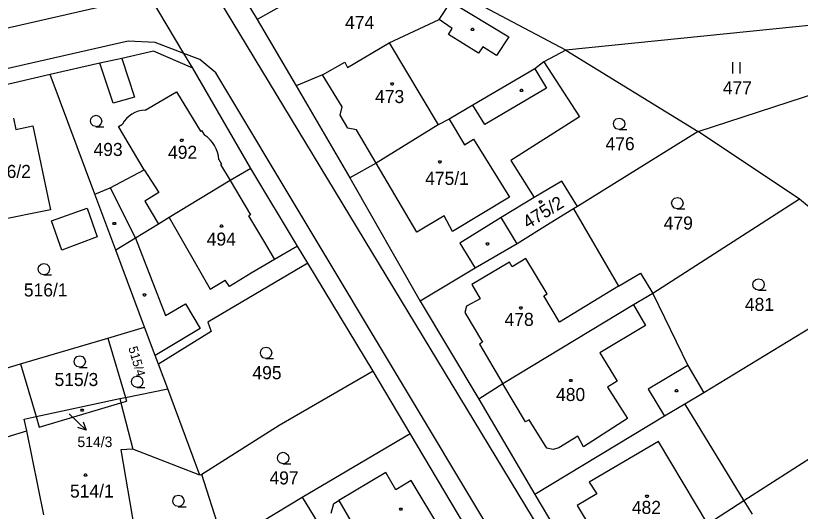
# Model space of a CAD drawing. Extents: x -621797 to -620972, y -1175539 to -1174697.
# Drawn here: x -621483.9 to -621381.7, y -1174869.1 to -1174804.6 of the extents above; entities that cross this region are included whole.
import ezdxf

# ---------------------------------------------------------------- set-up
doc = ezdxf.new("R2010")
doc.units = 0
for name, color, linetype in [('INZ mimo EON - nadz', 7, 'Continuous'), ('Rozvod plynu EON', 7, 'Continuous'), ('SDEL EON', 7, 'Continuous'), ('SDEL EON - popis', 7, 'Continuous'), ('Silnoproud EON', 7, 'Continuous'), ('Silnoproud EON - popis', 7, 'Continuous')]:
    doc.layers.add(name, color=color, linetype=linetype)

msp = doc.modelspace()

# ---------------------------------------------------------------- linework, layer by layer
at = {"layer": 'INZ mimo EON - nadz'}
for p in [(-621476.92, -1174856.48), (-621474.718, -1174858.549)]:
    msp.add_line(p, (-621476.9, -1174856.49), dxfattribs=at)
msp.add_lwpolyline([(-621475.102, -1174857.499), (-621474.718, -1174858.549), (-621475.789, -1174858.226)], dxfattribs=at)
at = {"layer": 'Rozvod plynu EON'}
for points in [[(-621424.32, -1174806.24), (-621424.23, -1174806.39), (-621424.32, -1174806.54), (-621424.5, -1174806.54), (-621424.59, -1174806.39), (-621424.5, -1174806.24)], [(-621434.78, -1174813.34), (-621434.69, -1174813.49), (-621434.78, -1174813.64), (-621434.96, -1174813.64), (-621435.05, -1174813.49), (-621434.96, -1174813.34)], [(-621417.95, -1174814.18), (-621417.86, -1174814.33), (-621417.95, -1174814.48), (-621418.13, -1174814.48), (-621418.22, -1174814.33), (-621418.13, -1174814.18)], [(-621462.18, -1174820.67), (-621462.09, -1174820.82), (-621462.18, -1174820.97), (-621462.36, -1174820.97), (-621462.45, -1174820.82), (-621462.36, -1174820.67)], [(-621428.58, -1174823.49), (-621428.49, -1174823.64), (-621428.58, -1174823.79), (-621428.76, -1174823.79), (-621428.85, -1174823.64), (-621428.76, -1174823.49)], [(-621415.48, -1174828.7), (-621415.39, -1174828.85), (-621415.48, -1174829), (-621415.66, -1174829), (-621415.75, -1174828.85), (-621415.66, -1174828.7)], [(-621470.95, -1174831.51), (-621470.86, -1174831.66), (-621470.95, -1174831.81), (-621471.13, -1174831.81), (-621471.22, -1174831.66), (-621471.13, -1174831.51)], [(-621457.01, -1174831.85), (-621456.92, -1174832), (-621457.01, -1174832.15), (-621457.19, -1174832.15), (-621457.28, -1174832), (-621457.19, -1174831.85)], [(-621422.36, -1174834.16), (-621422.27, -1174834.31), (-621422.36, -1174834.46), (-621422.54, -1174834.46), (-621422.63, -1174834.31), (-621422.54, -1174834.16)], [(-621467.03, -1174840.81), (-621466.94, -1174840.96), (-621467.03, -1174841.11), (-621467.21, -1174841.11), (-621467.3, -1174840.96), (-621467.21, -1174840.81)], [(-621418.02, -1174842.51), (-621417.93, -1174842.66), (-621418.02, -1174842.81), (-621418.2, -1174842.81), (-621418.29, -1174842.66), (-621418.2, -1174842.51)], [(-621411.53, -1174851.95), (-621411.44, -1174852.1), (-621411.53, -1174852.25), (-621411.71, -1174852.25), (-621411.8, -1174852.1), (-621411.71, -1174851.95)], [(-621397.77, -1174853.29), (-621397.68, -1174853.44), (-621397.77, -1174853.59), (-621397.95, -1174853.59), (-621398.04, -1174853.44), (-621397.95, -1174853.29)], [(-621475.13, -1174855.81), (-621475.04, -1174855.96), (-621475.13, -1174856.11), (-621475.31, -1174856.11), (-621475.4, -1174855.96), (-621475.31, -1174855.81)], [(-621474.72, -1174864.27), (-621474.63, -1174864.42), (-621474.72, -1174864.57), (-621474.9, -1174864.57), (-621474.99, -1174864.42), (-621474.9, -1174864.27)], [(-621401.6, -1174867.01), (-621401.51, -1174867.16), (-621401.6, -1174867.31), (-621401.78, -1174867.31), (-621401.87, -1174867.16), (-621401.78, -1174867.01)], [(-621433.66, -1174868.7), (-621433.57, -1174868.85), (-621433.66, -1174869), (-621433.84, -1174869), (-621433.93, -1174868.85), (-621433.84, -1174868.7)]]:
    msp.add_lwpolyline(points, close=True, dxfattribs=at)
at = {"layer": 'SDEL EON'}
for p, q in [((-621390.54, -1174810.65), (-621390.54, -1174812.15)), ((-621389.54, -1174812.15), (-621389.54, -1174810.65))]:
    msp.add_line(p, q, dxfattribs=at)
for points in [[(-621473.41, -1174819.05), (-621473.79, -1174818.95), (-621474.06, -1174818.68), (-621474.16, -1174818.31), (-621474.06, -1174817.94), (-621473.79, -1174817.67), (-621473.42, -1174817.57), (-621473.05, -1174817.67), (-621472.78, -1174817.94), (-621472.68, -1174818.32), (-621472.78, -1174818.7), (-621473.05, -1174818.97), (-621473.43, -1174819.07), (-621472.43, -1174819.07)], [(-621405.31, -1174819.42), (-621405.69, -1174819.32), (-621405.96, -1174819.05), (-621406.06, -1174818.68), (-621405.96, -1174818.31), (-621405.69, -1174818.04), (-621405.32, -1174817.94), (-621404.95, -1174818.04), (-621404.68, -1174818.31), (-621404.58, -1174818.69), (-621404.68, -1174819.07), (-621404.95, -1174819.34), (-621405.33, -1174819.44), (-621404.33, -1174819.44)], [(-621397.73, -1174829.75), (-621398.11, -1174829.65), (-621398.38, -1174829.38), (-621398.48, -1174829.01), (-621398.38, -1174828.64), (-621398.11, -1174828.37), (-621397.74, -1174828.27), (-621397.37, -1174828.37), (-621397.1, -1174828.64), (-621397, -1174829.02), (-621397.1, -1174829.4), (-621397.37, -1174829.67), (-621397.75, -1174829.77), (-621396.75, -1174829.77)], [(-621480.21, -1174838.34), (-621480.59, -1174838.24), (-621480.86, -1174837.97), (-621480.96, -1174837.6), (-621480.86, -1174837.23), (-621480.59, -1174836.96), (-621480.22, -1174836.86), (-621479.85, -1174836.96), (-621479.58, -1174837.23), (-621479.48, -1174837.61), (-621479.58, -1174837.99), (-621479.85, -1174838.26), (-621480.23, -1174838.36), (-621479.23, -1174838.36)], [(-621387.16, -1174840.34), (-621387.54, -1174840.24), (-621387.81, -1174839.97), (-621387.91, -1174839.6), (-621387.81, -1174839.23), (-621387.54, -1174838.96), (-621387.17, -1174838.86), (-621386.8, -1174838.96), (-621386.53, -1174839.23), (-621386.43, -1174839.61), (-621386.53, -1174839.99), (-621386.8, -1174840.26), (-621387.18, -1174840.36), (-621386.18, -1174840.36)], [(-621451.28, -1174849.23), (-621451.66, -1174849.13), (-621451.93, -1174848.86), (-621452.03, -1174848.49), (-621451.93, -1174848.12), (-621451.66, -1174847.85), (-621451.29, -1174847.75), (-621450.92, -1174847.85), (-621450.65, -1174848.12), (-621450.55, -1174848.5), (-621450.65, -1174848.88), (-621450.92, -1174849.15), (-621451.3, -1174849.25), (-621450.3, -1174849.25)], [(-621475.54, -1174850.37), (-621475.92, -1174850.27), (-621476.19, -1174850), (-621476.29, -1174849.63), (-621476.19, -1174849.26), (-621475.92, -1174848.99), (-621475.55, -1174848.89), (-621475.18, -1174848.99), (-621474.91, -1174849.26), (-621474.81, -1174849.64), (-621474.91, -1174850.02), (-621475.18, -1174850.29), (-621475.56, -1174850.39), (-621474.56, -1174850.39)], [(-621468.06, -1174853), (-621468.44, -1174852.9), (-621468.71, -1174852.63), (-621468.81, -1174852.26), (-621468.71, -1174851.89), (-621468.44, -1174851.62), (-621468.07, -1174851.52), (-621467.7, -1174851.62), (-621467.43, -1174851.89), (-621467.33, -1174852.27), (-621467.43, -1174852.65), (-621467.7, -1174852.92), (-621468.08, -1174853.02), (-621467.08, -1174853.02)], [(-621449.06, -1174862.93), (-621449.44, -1174862.83), (-621449.71, -1174862.56), (-621449.81, -1174862.19), (-621449.71, -1174861.82), (-621449.44, -1174861.55), (-621449.07, -1174861.45), (-621448.7, -1174861.55), (-621448.43, -1174861.82), (-621448.33, -1174862.2), (-621448.43, -1174862.58), (-621448.7, -1174862.85), (-621449.08, -1174862.95), (-621448.08, -1174862.95)], [(-621462.69, -1174868.51), (-621463.07, -1174868.41), (-621463.34, -1174868.14), (-621463.44, -1174867.77), (-621463.34, -1174867.4), (-621463.07, -1174867.13), (-621462.7, -1174867.03), (-621462.33, -1174867.13), (-621462.06, -1174867.4), (-621461.96, -1174867.78), (-621462.06, -1174868.16), (-621462.33, -1174868.43), (-621462.71, -1174868.53), (-621461.71, -1174868.53)]]:
    msp.add_lwpolyline(points, dxfattribs=at)
at = {"layer": 'SDEL EON - popis'}
for p, q in [((-621461.85, -1174795.25), (-621402.58, -1174893.11)), ((-621470.29, -1174802.9), (-621493.86, -1174808.23)), ((-621427.21, -1174802.78), (-621419.69, -1174807.36)), ((-621427.04, -1174806.26), (-621428.73, -1174805.08)), ((-621427.53, -1174807.05), (-621427.04, -1174806.26)), ((-621423.62, -1174809.49), (-621427.53, -1174807.05)), ((-621469.26, -1174807.94), (-621494.45, -1174813.64)), ((-621465.74, -1174808.08), (-621469.26, -1174807.94)), ((-621461.99, -1174809.51), (-621465.74, -1174808.08)), ((-621435.27, -1174808.14), (-621428.88, -1174818.81)), ((-621419.69, -1174807.36), (-621421.27, -1174809.78)), ((-621423.08, -1174808.64), (-621423.62, -1174809.49)), ((-621421.27, -1174809.78), (-621423.08, -1174808.64)), ((-621470.08, -1174810.16), (-621468.43, -1174815.23)), ((-621459.93, -1174810.3), (-621461.99, -1174809.51)), ((-621457.84, -1174812.05), (-621459.93, -1174810.3)), ((-621471.21, -1174815.98), (-621472.93, -1174810.8)), ((-621392.36, -1174921.13), (-621457.84, -1174812.05)), ((-621443.95, -1174812.29), (-621447.38, -1174813.75)), ((-621416.28, -1174811.51), (-621414.78, -1174814.06)), ((-621414.78, -1174814.06), (-621422.81, -1174818.77)), ((-621468.43, -1174815.23), (-621471.21, -1174815.98)), ((-621422.81, -1174818.77), (-621424.37, -1174816.27)), ((-621427.44, -1174818.06), (-621425.44, -1174821.41)), ((-621425.44, -1174821.41), (-621424.28, -1174820.7)), ((-621424.28, -1174820.7), (-621419.61, -1174828.25)), ((-621467.15, -1174824.67), (-621465.25, -1174827.64)), ((-621431.67, -1174832.78), (-621436.97, -1174823.79)), ((-621455.96, -1174826.08), (-621453.31, -1174830.52)), ((-621471.6, -1174827.03), (-621468.28, -1174833.55)), ((-621465.25, -1174827.64), (-621467.05, -1174828.75)), ((-621467.05, -1174828.75), (-621465.29, -1174831.73)), ((-621419.61, -1174828.25), (-621427.01, -1174832.68)), ((-621479.22, -1174831.31), (-621474.57, -1174829.67)), ((-621474.57, -1174829.67), (-621473.28, -1174833.39)), ((-621453.31, -1174830.52), (-621453.56, -1174830.68)), ((-621453.56, -1174830.68), (-621451.63, -1174833.91)), ((-621428.09, -1174830.67), (-621431.67, -1174832.78)), ((-621427.01, -1174832.68), (-621428.09, -1174830.67)), ((-621477.87, -1174835.14), (-621479.22, -1174831.31)), ((-621463.91, -1174830.89), (-621458.58, -1174840.2)), ((-621418.58, -1174834.29), (-621420.66, -1174830.86)), ((-621473.28, -1174833.39), (-621477.87, -1174835.14)), ((-621468.28, -1174833.55), (-621464.38, -1174843.62)), ((-621451.63, -1174833.91), (-621450.18, -1174836.35)), ((-621447.19, -1174834.59), (-621450.18, -1174836.35)), ((-621450.18, -1174836.35), (-621453.21, -1174838.14)), ((-621419.59, -1174836.71), (-621424.49, -1174839.62)), ((-621419.24, -1174837.29), (-621419.59, -1174836.71)), ((-621417.46, -1174836.23), (-621419.24, -1174837.29)), ((-621414.69, -1174840.81), (-621417.46, -1174836.23)), ((-621453.21, -1174838.14), (-621456.04, -1174839.88)), ((-621458.58, -1174840.2), (-621456.62, -1174839.03)), ((-621456.04, -1174839.88), (-621456.62, -1174839.03)), ((-621424.49, -1174839.62), (-621423.43, -1174841.45)), ((-621405.38, -1174839.83), (-621413.08, -1174844.49)), ((-621415.12, -1174841.06), (-621414.69, -1174840.81)), ((-621413.08, -1174844.49), (-621415.12, -1174841.06)), ((-621423.43, -1174841.45), (-621425.17, -1174842.43)), ((-621464.38, -1174843.62), (-621461.77, -1174842.1)), ((-621461.77, -1174842.1), (-621459.85, -1174845.33)), ((-621425.17, -1174842.43), (-621425.4, -1174843.24)), ((-621403.43, -1174842.24), (-621401.87, -1174844.94)), ((-621425.4, -1174843.24), (-621423.12, -1174847.09)), ((-621401.87, -1174844.94), (-621407.81, -1174848.5)), ((-621459.85, -1174845.33), (-621465.73, -1174848.83)), ((-621423.12, -1174847.09), (-621423.52, -1174847.39)), ((-621423.52, -1174847.39), (-621420.46, -1174852.54)), ((-621407.81, -1174848.5), (-621405.59, -1174852.18)), ((-621396.36, -1174850.15), (-621401.55, -1174853.22)), ((-621405.59, -1174852.18), (-621406.82, -1174852.97)), ((-621417.49, -1174857.5), (-621420.46, -1174852.54)), ((-621406.82, -1174852.97), (-621404.22, -1174857.05)), ((-621401.55, -1174853.22), (-621399.43, -1174856.74)), ((-621470.33, -1174854.45), (-621470.18, -1174855.02)), ((-621470.18, -1174855.02), (-621468.62, -1174861.06)), ((-621417.03, -1174857.22), (-621417.49, -1174857.5)), ((-621414.72, -1174860.93), (-621417.03, -1174857.22)), ((-621404.22, -1174857.05), (-621409.94, -1174860.73)), ((-621410.68, -1174859.34), (-621413.15, -1174860.88)), ((-621409.94, -1174860.73), (-621410.68, -1174859.34)), ((-621400.21, -1174860.03), (-621409.2, -1174865.35)), ((-621393.76, -1174870.81), (-621400.21, -1174860.03)), ((-621413.92, -1174861.09), (-621414.72, -1174860.93)), ((-621413.15, -1174860.88), (-621413.92, -1174861.09)), ((-621435.71, -1174864.09), (-621441.83, -1174867.74)), ((-621434.4, -1174866.33), (-621435.71, -1174864.09)), ((-621432.38, -1174865.12), (-621434.4, -1174866.33)), ((-621427.89, -1174872.59), (-621432.38, -1174865.12)), ((-621409.2, -1174865.35), (-621408.22, -1174866.85)), ((-621408.22, -1174866.85), (-621410.77, -1174868.36)), ((-621410.77, -1174868.36), (-621407.68, -1174873.5))]:
    msp.add_line(p, q, dxfattribs=at)
at = {"layer": 'Silnoproud EON'}
for p, q in [((-621458.69, -1174794.8), (-621452.45, -1174805.11)), ((-621461.99, -1174809.51), (-621468.3, -1174798.95)), ((-621445.02, -1174800.92), (-621452.45, -1174805.11)), ((-621412.27, -1174809.1), (-621426.41, -1174801.58)), ((-621428.73, -1174805.08), (-621427.21, -1174802.78)), ((-621452.45, -1174805.11), (-621447.38, -1174813.75)), ((-621435.27, -1174808.14), (-621428.73, -1174805.08)), ((-621378.63, -1174805.68), (-621412.27, -1174809.1)), ((-621440.69, -1174811.33), (-621435.27, -1174808.14)), ((-621465.93, -1174809.22), (-621470.08, -1174810.16)), ((-621460.83, -1174811.45), (-621465.93, -1174809.22)), ((-621412.27, -1174809.1), (-621415.12, -1174810.61)), ((-621412.27, -1174809.1), (-621395.03, -1174819.7)), ((-621470.08, -1174810.16), (-621472.93, -1174810.8)), ((-621460.83, -1174811.45), (-621461.99, -1174809.51)), ((-621472.93, -1174810.8), (-621479.38, -1174812.26)), ((-621443.95, -1174812.29), (-621441.05, -1174810.67)), ((-621441.05, -1174810.67), (-621440.69, -1174811.33)), ((-621415.12, -1174810.61), (-621416.28, -1174811.51)), ((-621415.12, -1174810.61), (-621410.46, -1174817.79)), ((-621395.03, -1174819.7), (-621368.11, -1174810.87)), ((-621479.38, -1174812.26), (-621494.01, -1174815.67)), ((-621473.56, -1174827.86), (-621479.38, -1174812.26)), ((-621453.27, -1174824.51), (-621460.83, -1174811.45)), ((-621441.36, -1174816.49), (-621443.95, -1174812.29)), ((-621416.28, -1174811.51), (-621424.37, -1174816.27)), ((-621447.38, -1174813.75), (-621440.36, -1174825.71)), ((-621467.01, -1174816.92), (-621462.95, -1174814.52)), ((-621462.95, -1174814.52), (-621459.81, -1174819.63)), ((-621441.64, -1174817.55), (-621441.36, -1174816.49)), ((-621424.37, -1174816.27), (-621427.44, -1174818.06)), ((-621440.65, -1174819.26), (-621441.64, -1174817.55)), ((-621484.15, -1174817.93), (-621483.85, -1174819.4)), ((-621427.44, -1174818.06), (-621428.88, -1174818.81)), ((-621410.46, -1174817.79), (-621419.4, -1174823.44)), ((-621483.85, -1174819.4), (-621481.66, -1174818.95)), ((-621481.66, -1174818.95), (-621479.34, -1174829.86)), ((-621470.51, -1174819.04), (-621469.98, -1174818.74)), ((-621467.15, -1174824.67), (-621470.51, -1174819.04)), ((-621459.81, -1174819.63), (-621459.7, -1174819.56)), ((-621459.7, -1174819.56), (-621459.31, -1174820.15)), ((-621439.53, -1174819.46), (-621440.65, -1174819.26)), ((-621436.97, -1174823.79), (-621439.53, -1174819.46)), ((-621428.88, -1174818.81), (-621436.97, -1174823.79)), ((-621395.03, -1174819.7), (-621410.75, -1174829.44)), ((-621381.84, -1174828.51), (-621395.03, -1174819.7)), ((-621457.45, -1174823.31), (-621457.11, -1174823.94)), ((-621419.4, -1174823.44), (-621416.37, -1174828.29)), ((-621471.6, -1174827.03), (-621467.15, -1174824.67)), ((-621457.11, -1174823.94), (-621457.2, -1174823.99)), ((-621457.2, -1174823.99), (-621455.96, -1174826.08)), ((-621453.27, -1174824.51), (-621455.96, -1174826.08)), ((-621447.19, -1174834.59), (-621453.27, -1174824.51)), ((-621436.97, -1174823.79), (-621440.36, -1174825.71)), ((-621440.36, -1174825.71), (-621431.21, -1174841.79)), ((-621455.96, -1174826.08), (-621463.91, -1174830.89)), ((-621412.79, -1174826.15), (-621416.37, -1174828.29)), ((-621410.75, -1174829.44), (-621412.79, -1174826.15)), ((-621473.56, -1174827.86), (-621471.6, -1174827.03)), ((-621470.86, -1174835.13), (-621473.56, -1174827.86)), ((-621416.37, -1174828.29), (-621420.66, -1174830.86)), ((-621381.84, -1174828.51), (-621400.92, -1174840.77)), ((-621369.48, -1174838.62), (-621381.84, -1174828.51)), ((-621411.24, -1174829.74), (-621414.29, -1174831.63)), ((-621410.75, -1174829.44), (-621411.24, -1174829.74)), ((-621411.24, -1174829.74), (-621405.38, -1174839.83)), ((-621479.34, -1174829.86), (-621488.2, -1174831.67)), ((-621465.29, -1174831.73), (-621468.28, -1174833.55)), ((-621463.91, -1174830.89), (-621465.29, -1174831.73)), ((-621420.66, -1174830.86), (-621426.07, -1174834.2)), ((-621414.29, -1174831.63), (-621418.58, -1174834.29)), ((-621468.28, -1174833.55), (-621470.86, -1174835.13)), ((-621445.84, -1174836.81), (-621447.19, -1174834.59)), ((-621426.07, -1174834.2), (-621424.07, -1174837.49)), ((-621418.58, -1174834.29), (-621424.07, -1174837.49)), ((-621467.1, -1174845.15), (-621470.86, -1174835.13)), ((-621445.84, -1174836.81), (-621458.85, -1174844.5)), ((-621437.35, -1174850.88), (-621445.84, -1174836.81)), ((-621424.07, -1174837.49), (-621431.21, -1174841.79)), ((-621405.38, -1174839.83), (-621402.54, -1174838.11)), ((-621402.54, -1174838.11), (-621400.92, -1174840.77)), ((-621369.48, -1174838.62), (-621394.29, -1174853.7)), ((-621400.92, -1174840.77), (-621403.43, -1174842.24)), ((-621400.92, -1174840.77), (-621396.36, -1174850.15)), ((-621431.21, -1174841.79), (-621423.58, -1174854.55)), ((-621403.43, -1174842.24), (-621420.46, -1174852.54)), ((-621471.89, -1174846.57), (-621467.1, -1174845.15)), ((-621465.73, -1174848.83), (-621467.1, -1174845.15)), ((-621458.85, -1174844.5), (-621458.44, -1174845.73)), ((-621458.44, -1174845.73), (-621465.3, -1174849.96)), ((-621483.27, -1174849.95), (-621471.89, -1174846.57)), ((-621471.89, -1174846.57), (-621469.6, -1174854.3)), ((-621357.36, -1174847.45), (-621389.1, -1174867.76)), ((-621465.3, -1174849.96), (-621465.73, -1174848.83)), ((-621487.76, -1174851.28), (-621483.27, -1174849.95)), ((-621483.27, -1174849.95), (-621481.24, -1174856.8)), ((-621464.09, -1174853.2), (-621465.3, -1174849.96)), ((-621396.36, -1174850.15), (-621394.29, -1174853.7)), ((-621437.35, -1174850.88), (-621449.58, -1174857.97)), ((-621432.52, -1174858.98), (-621437.35, -1174850.88)), ((-621469.6, -1174854.3), (-621464.09, -1174853.2)), ((-621459.9, -1174864.42), (-621464.09, -1174853.2)), ((-621420.46, -1174852.54), (-621423.58, -1174854.55)), ((-621470.33, -1174854.45), (-621469.6, -1174854.3)), ((-621469.6, -1174854.3), (-621469.45, -1174854.81)), ((-621394.29, -1174853.7), (-621396.78, -1174855.17)), ((-621481.24, -1174856.8), (-621470.33, -1174854.45)), ((-621480.83, -1174858.18), (-621470.18, -1174855.02)), ((-621470.18, -1174855.02), (-621469.45, -1174854.81)), ((-621423.58, -1174854.55), (-621416.3, -1174866.94)), ((-621396.78, -1174855.17), (-621399.43, -1174856.74)), ((-621396.78, -1174855.17), (-621389.1, -1174867.76)), ((-621482.76, -1174857.13), (-621481.24, -1174856.8)), ((-621482.45, -1174858.66), (-621482.76, -1174857.13)), ((-621481.24, -1174856.8), (-621480.83, -1174858.18)), ((-621399.43, -1174856.74), (-621416.3, -1174866.94)), ((-621449.58, -1174857.97), (-621459.66, -1174864.35)), ((-621486.02, -1174859.72), (-621482.45, -1174858.66)), ((-621480.21, -1174869.59), (-621482.45, -1174858.66)), ((-621446.59, -1174867.29), (-621432.52, -1174858.98)), ((-621425.39, -1174870.96), (-621432.52, -1174858.98)), ((-621468.62, -1174861.06), (-621470.18, -1174861.13)), ((-621470.18, -1174861.13), (-621468.34, -1174872.07)), ((-621459.9, -1174864.42), (-621468.62, -1174861.06)), ((-621459.66, -1174864.35), (-621459.9, -1174864.42)), ((-621456.42, -1174874.43), (-621459.66, -1174864.35)), ((-621451.73, -1174870.41), (-621446.59, -1174867.29)), ((-621446.59, -1174867.29), (-621444.54, -1174870.63)), ((-621416.3, -1174866.94), (-621408.65, -1174879.68)), ((-621442.82, -1174869.35), (-621442.45, -1174868.11)), ((-621442.45, -1174868.11), (-621441.83, -1174867.74)), ((-621441.83, -1174867.74), (-621440.25, -1174870.4)), ((-621389.1, -1174867.76), (-621393.76, -1174870.81)), ((-621389.1, -1174867.76), (-621387.99, -1174869.52))]:
    msp.add_line(p, q, dxfattribs=at)
for centre, radius, start, end in [((-621467.036, -1174820.211), 3.291, 89.55038, 153.44911), ((-621461.351, -1174823.479), 3.905, 2.4803, 58.48248)]:
    msp.add_arc(centre, radius, start, end, dxfattribs=at)

# ---------------------------------------------------------------- texts
at = {"layer": 'INZ mimo EON - nadz'}
msp.add_text('514/3', height=1.36, dxfattribs=at).set_placement((-621475.845, -1174860.77))
at = {"layer": 'Silnoproud EON - popis'}
for s, height, p in [('474', 1.7, (-621441.003, -1174806.33)), ('477', 1.7, (-621391.823, -1174814.85)), ('473', 1.7, (-621437.093, -1174815.98)), ('476', 1.7, (-621407.093, -1174822.12)), ('493', 1.7, (-621473.753, -1174822.87)), ('492', 1.7, (-621464.053, -1174823.24)), ('516/2', 1.7, (-621487.593, -1174825.73)), ('475/1', 1.7, (-621430.573, -1174826.63)), ('479', 1.7, (-621399.513, -1174832.45)), ('494', 1.7, (-621459.013, -1174834.54)), ('516/1', 1.7, (-621482.823, -1174841.16)), ('481', 1.7, (-621388.943, -1174843.04)), ('478', 1.7, (-621420.233, -1174844.99)), ('495', 1.7, (-621453.063, -1174851.93)), ('515/3', 1.7, (-621478.823, -1174852.82)), ('480', 1.7, (-621413.533, -1174854.77)), ('514/3', 0.1, (-621477.109, -1174856.48)), ('497', 1.7, (-621450.843, -1174865.63)), ('514/1', 1.7, (-621476.813, -1174867.34)), ('482', 1.7, (-621403.663, -1174869.47))]:
    msp.add_text(s, height=height, dxfattribs=at).set_placement(p)
for s, height, rotation, p in [('475/2', 1.7, 31.51268, (-621417.198, -1174832.396)), ('515/4', 1.2, 286.19242, (-621469.233, -1174847.841))]:
    msp.add_text(s, height=height, rotation=rotation, dxfattribs=at).set_placement(p)

doc.saveas('drawing.dxf')
